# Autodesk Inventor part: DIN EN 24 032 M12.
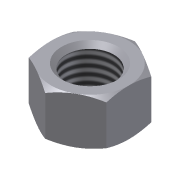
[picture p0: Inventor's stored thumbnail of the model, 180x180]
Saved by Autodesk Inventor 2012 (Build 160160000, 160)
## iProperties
Shininess: 20.0
Length Units: 11269
Angle Units: 11279
Time Units: 11290
Mass Units: 11283
Length Display Precision: 3
Angle Display Precision: 2
Company: CAD-Verlag
Created: 2001-01
Part Number: DIN EN 24 032 M12.
Material: Steel, Mild
Document SubType Name: Modeling
Description: Mutter DIN EN 24 032 M12.
Standard: DIN EN 24 032
Density: 7.86 g/cm^3
Density: 7.86
Volumn: 1.1364084233749536
Area: 9.602775185060906
PropertySet Name: Model Information
Control State: 0
Master: False
Checked Out: False
Author: Jürgen Kronas
Revision Number: 2
BOM1: Mutter
BOM2: M12
BOM3: DIN EN 24 032
+MSCProtocol1+ProtocolID: P00040924060732003
+MSCProtocol2+Protocol: P00040924060732003<@PID>[Version]<@EL>Version=2.2<@EL>[Data]<@EL>mass=0.014205{kg<@EL>m=10.8{mm<@EL>s=18{mm<@EL>d=12{mm<@EL>P=1.75{mm<@EL>[Files]<@EL>DataFile=S
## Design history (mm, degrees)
node "WorkPlane8"
node "WorkPlane10"
sketch "Sketch1"
  geometry: 1 further point
node "WorkPoint1"
sketch "Sketch2" dims "d2" = 16.2 (= -0.15 x prf_d + prf_s)
  geometry: C1 r 5 at (0, 0) reference; A1 r 8 centre (0, 0) between (-4, 6.928) and (-8, 0) reference; A2 r 8 centre (0, 0) between (4, 6.928) and (-4, 6.928) reference; A3 r 8 centre (0, 0) between (8, 0) and (4, 6.928) reference; A4 r 8 centre (0, 0) between (4, -6.928) and (8, 0) reference; A5 r 8 centre (0, 0) between (-4, -6.928) and (4, -6.928) reference; A6 r 8 centre (0, 0) between (-8, 0) and (-4, -6.928) reference; 1 further point
extrude "ExtrusionBlind1" new body sketch "Sketch2" distance "d3" = 10.8 (= prf_m); taper "d4" = 0 deg
sketch "Sketch3"
  geometry: 1 further point
node "WorkPoint2"
sketch "Sketch4"
  geometry: L1 (9, -5.196)-(9, 5.196); L2 (0, -10.392)-(9, -5.196); L3 (-9, -5.196)-(0, -10.392); L4 (-9, 5.196)-(-9, -5.196); L5 (0, 10.392)-(-9, 5.196); L6 (9, 5.196)-(0, 10.392); C1 r 9 at (0, 0); C2 r 8.1 at (0, 0) reference
  constraints: 12 end point, 6 tangent, 2 parallel, 2 vertical, 1 centre point, 1 concentric
  dimensions: "d8" = 18 diameter of C1 (= prf_s)
extrude "ExtrusionBlind2" join sketch "Sketch4" distance "d9" = 10.8 (= prf_m); taper "d10" = 0 deg
sketch "Sketch6"
  geometry: L1 (-10.392, -9.996)-(-9, -10.8); L2 (0, -12.96)-(0, 2.16) reference; L3 (-10.392, -9.996)-(-10.392, -10.8); L4 (-10.392, -10.8)-(-9, -10.8); L5 (-10.392, 0)-(-10.392, -10.8) reference
  constraints: 6 end point, 1 parallel, 1 perpendicular
  dimensions: "d32" = 9 distance from line of L2 L1.end (= 0.5 x prf_s); "d34" = 0 distance between parallel lines of L3 L5; "d36" = 0 distance from line of L5.end L4; "d37" = 120 deg angle of L5 L1
revolve "RevolutionFull1" sketch "Sketch6" stored, may be unused: angle "d21" = 360 deg
sketch "Sketch7"
  geometry: L1 (-10.392, 0)-(-10.392, -0.804); L2 (-9, 0)-(-10.392, 0); L3 (-10.392, -0.804)-(-9, 0); L4 (-10.392, 0)-(-10.392, -9.996) reference; L5 (0, -12.96)-(0, 2.16) reference
  constraints: 6 end point, 1 horizontal, 1 vertical
  dimensions: "d38" = 0 distance between parallel lines of L4 L1; "d39" = 0 distance from line of L4.start L2; "d40" = 9 distance from line of L5 L2.start (= d32); "d41" = 120 deg angle of L1 L3
revolve "RevolutionFull2" sketch "Sketch7" stored, may be unused: angle "d26" = 360 deg
sketch "Sketch8"
  geometry: A1 r 9 centre (0, 0) between (9, 0) and (4.5, 7.794) reference; 1 further point
  constraints: 1 coincident
hole "Ms_Hole" sketch "Sketch8" at (0, 0) diameter "d57" = 11.0528; stored, may be unused: countersink angle "d61" = 82 deg, drill point angle "d63" = 118 deg; dims "d58" = 6, "d59" = 4, "d60" = 2, "d62" = 8
node "MSC_PT1"
node "MSC_PT2"
node "MSC_PF1"
node "MSC_A1"
chamfer "Chamfer1" distance "d55" = 1.05 (= 0.6 x prf_p); stored, may be unused: second distance "d56" = 1.05 (= 0.6 x prf_p), angle "d65" = 45 deg
node "Volumenkörper1"
node "Volumenkörpern"
node "Oberflächenkörpern"
other parameters: "prf_d" = 12 [user parameter; used in 1 equation term], "prf_m" = 10.8 [user parameter; used in 3 equation terms], "prf_s" = 18 [user parameter; used in 3 equation terms], "d0" = -10.8 (computed from prf_m), "d1" = 14.5 (derived), "d5" = 0, "d7" = 16 (derived), "d15" = 30 deg (derived), "d17" = 0 (derived), "d18" = 0 (derived), "d19" = 0 (derived), "d20" = 0 (derived), "d22" = 30 deg (derived), "d24" = 0 (derived), "d25" = 0 (derived), "d52" = 0, "d53" = 0, "d54" = 0, "prf_p" = 1.75 [user parameter; used in 2 equation terms], "d64" = 0
